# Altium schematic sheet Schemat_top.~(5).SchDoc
size A4; Author: Michał Wojna; CompanyName: AGH; Revision: 1
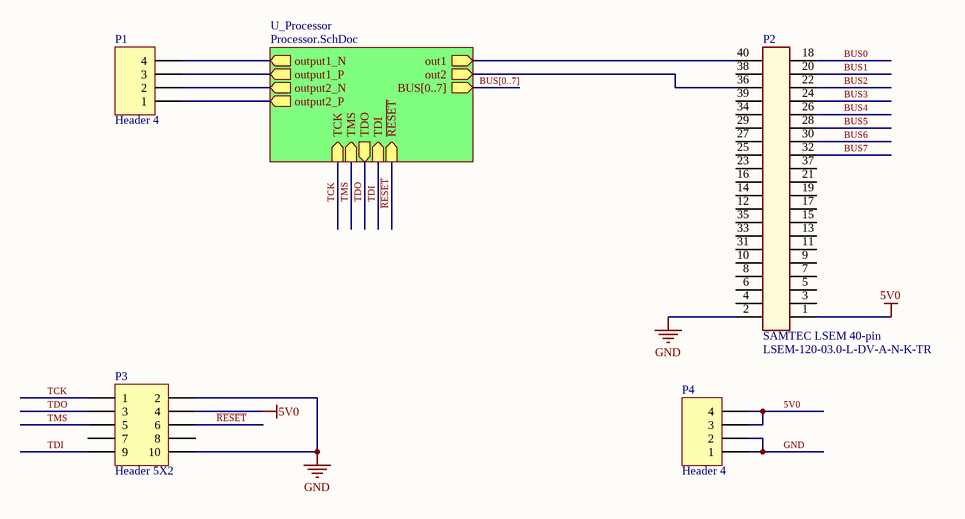
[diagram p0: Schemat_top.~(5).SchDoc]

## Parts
P1  Header 4  [HDR1X4]
P2  SAMTEC LSEM 40-pin  [LSEM-120-03.0-L-DV-A-N-K-TR]
P3  Header 5X2  [HDR2X5]
P4  Header 4  [HDR1X4]

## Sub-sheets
U_Processor = Processor.SchDoc: out1 (out), out2 (out), TCK (in), TMS (in), TDO (out), TDI (in), ~{RESET} (in), BUS[0..7] (out), output1_N (out), output1_P (out), output2_N (out), output2_P (out)

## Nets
5V0: P2.1(PIN) P3.4 P4.3 P4.4
GND: P2.2 P3.2 P3.10 P4.1 P4.2
BUS0: P2.18
BUS1: P2.20
BUS2: P2.22
BUS3: P2.24
BUS4: P2.26
BUS5: P2.28
BUS6: P2.30
BUS7: P2.32
~{RESET}: P3.6 ; sheet U_Processor/~{RESET}
TCK: P3.1 ; sheet U_Processor/TCK
TDI: P3.9 ; sheet U_Processor/TDI
TDO: P3.3 ; sheet U_Processor/TDO
TMS: P3.5 ; sheet U_Processor/TMS
NetP1_1: P1.1 ; sheet U_Processor/output2_P
NetP1_2: P1.2 ; sheet U_Processor/output2_N
NetP1_3: P1.3 ; sheet U_Processor/output1_P
NetP1_4: P1.4 ; sheet U_Processor/output1_N
NetP2_36: P2.36 ; sheet U_Processor/out2
NetP2_40: P2.40 ; sheet U_Processor/out1

Not connected (* = marked no-connect by the designer): P2 3(PIN) 4(3) 5(PIN) 6(4) 7(PIN) 8(5) 9(PIN) 10(6) 11(PIN) 12(7) 13(PIN) 14(8) 15(PIN) 16(9) 17(PIN) 19(PIN) 21(PIN) 23(PIN) 25(PIN) 27(PIN) 29(PIN) 31(PIN) 33(PIN) 34(18) 35(PIN) 37(PIN) 38(20) 39(PIN); P3 7 8

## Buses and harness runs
bus BUS[0..7] = sheet U_Processor/BUS[0..7]

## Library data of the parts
P1 P4 = Header 4: Header, 4-Pin
P2 = SAMTEC LSEM 40-pin: Component desciption
P3 = Header 5X2: Header, 5-Pin, Dual row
